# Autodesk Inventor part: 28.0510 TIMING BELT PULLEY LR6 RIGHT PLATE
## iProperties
Created: 2007-06
Part Number: 28.0510 TIMING BELT PULLEY LR6 RIGHT PLATE
Document SubType Name: Modeling
Designer: Andy Moles
Material: Aluminum-6061
Mass: 286.546 g
Surface Area: 352.02 cm^2
Volume: 105.736 cm^3
Density: 2.71 g/cm^3
Author: Andy Moles
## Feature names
1. Extrusion1
2. Hole1
3. Hole2
4. Extrusion2
5. Extrusion3
6. Extrusion4
7. Extrusion5
8. Extrusion6
9. Fillet1
10. Extrusion7
11. Extrusion8
12. Extrusion9
13. Extrusion10
14. Hole3
15. Extrusion11
16. Extrusion12
17. Extrusion13
18. Hole4
19. Extrusion14
20. Extrusion15
21. Extrusion16
22. Mirror1
